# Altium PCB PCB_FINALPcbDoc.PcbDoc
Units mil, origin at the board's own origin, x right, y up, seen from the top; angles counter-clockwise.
Board outline 2408.25 x 1826.41 mil, 2 copper layers (Top Layer, Bottom Layer); 49 components, 43 nets, 223 pads, 93 vias.
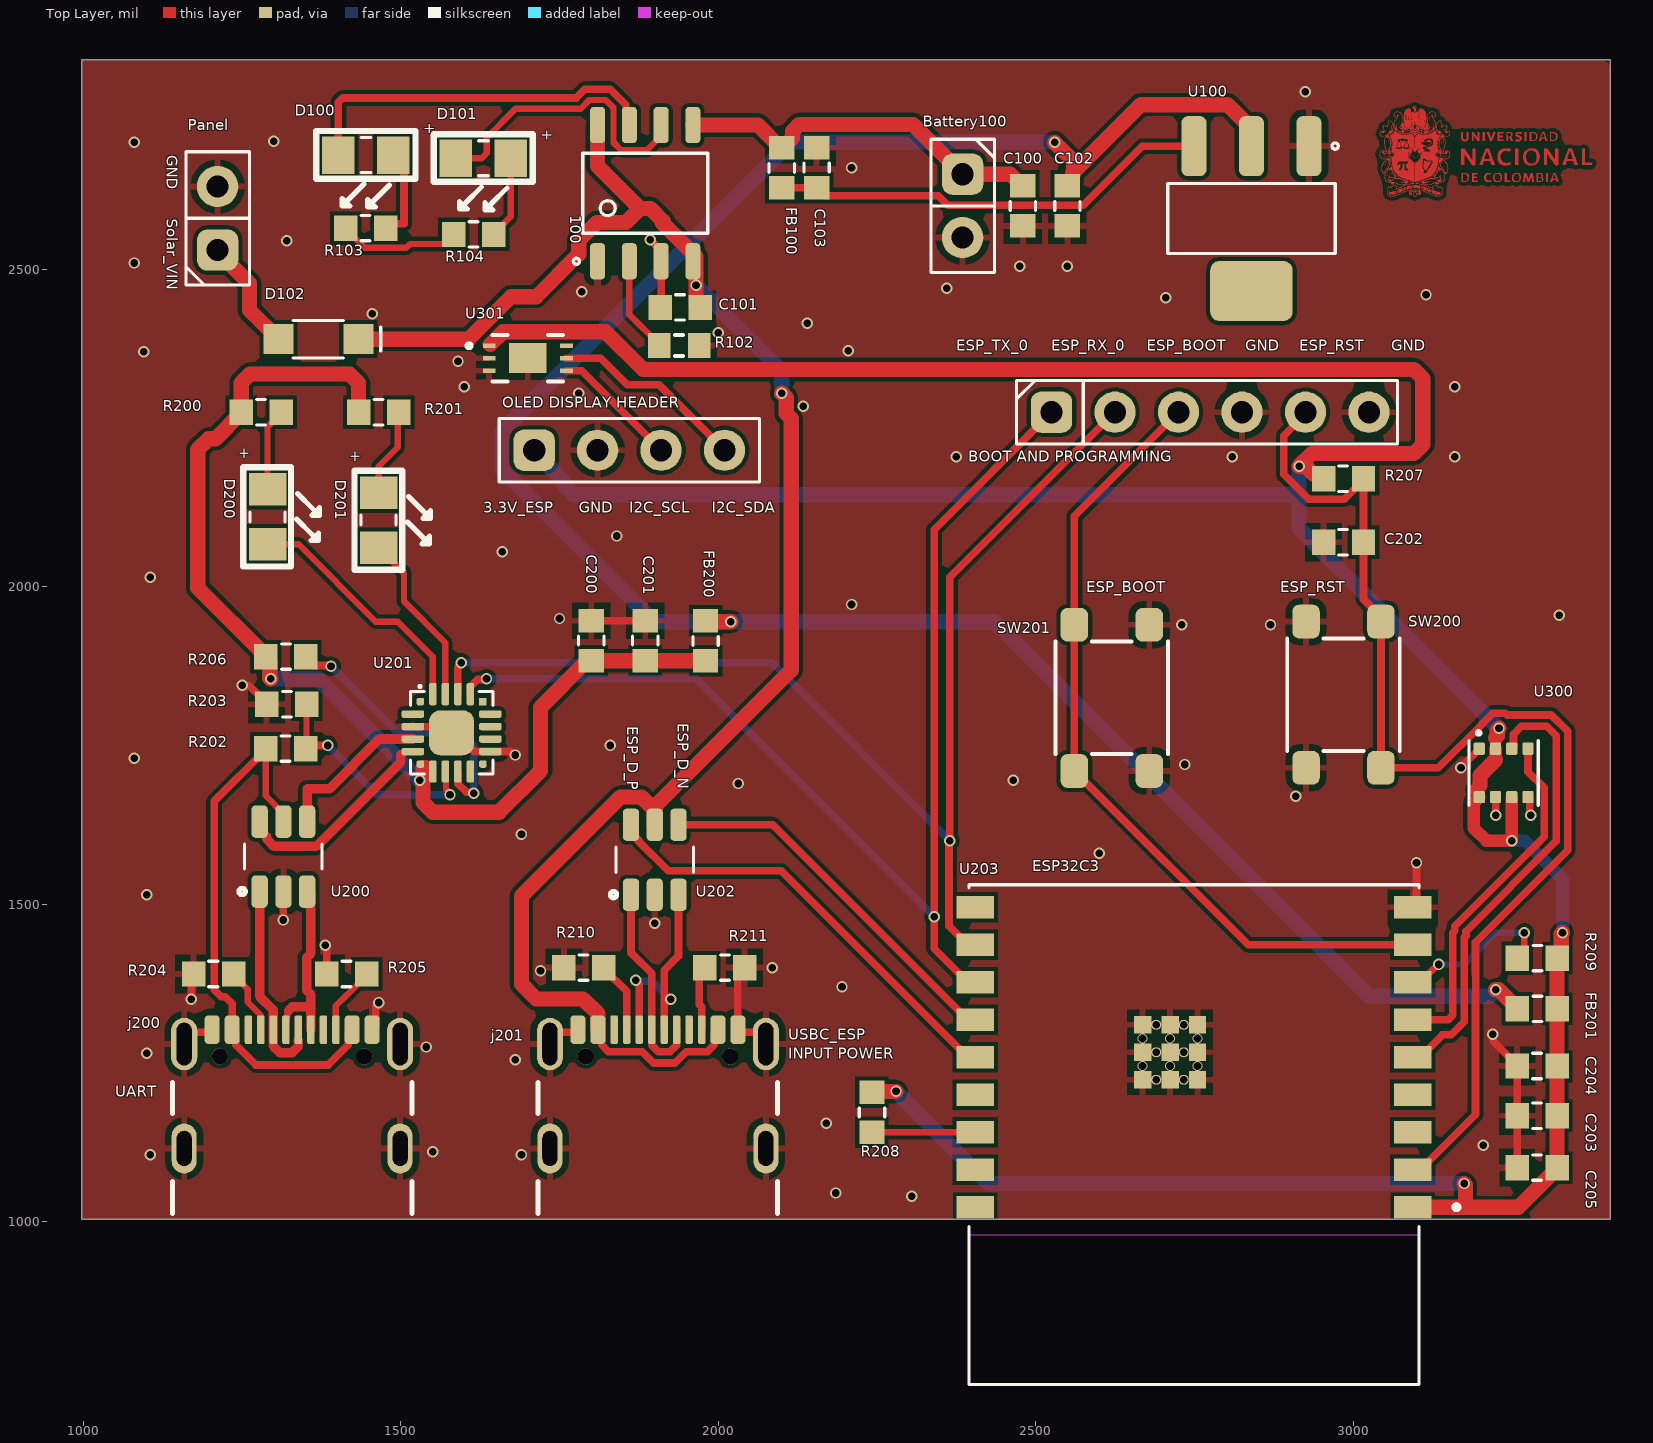
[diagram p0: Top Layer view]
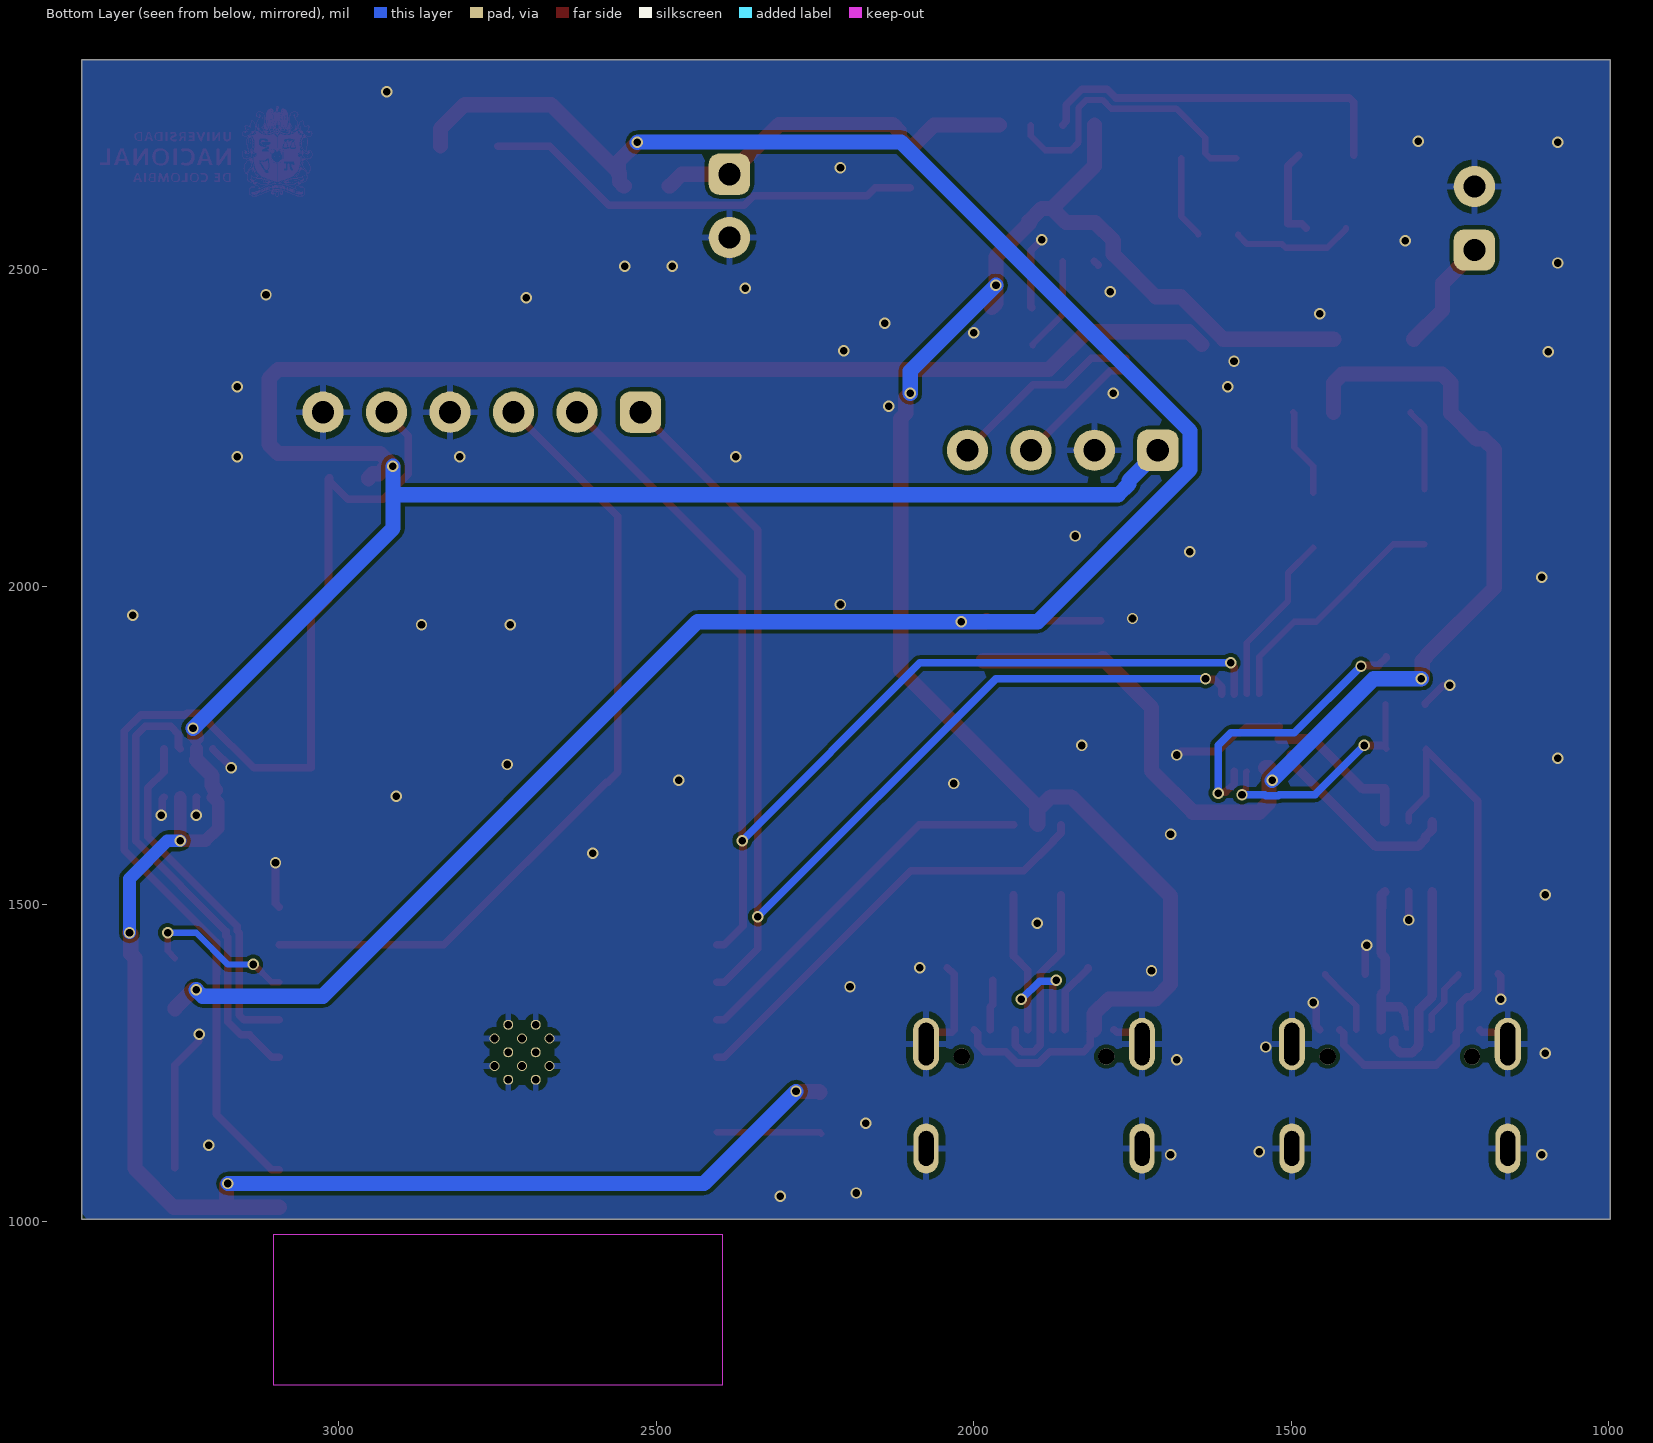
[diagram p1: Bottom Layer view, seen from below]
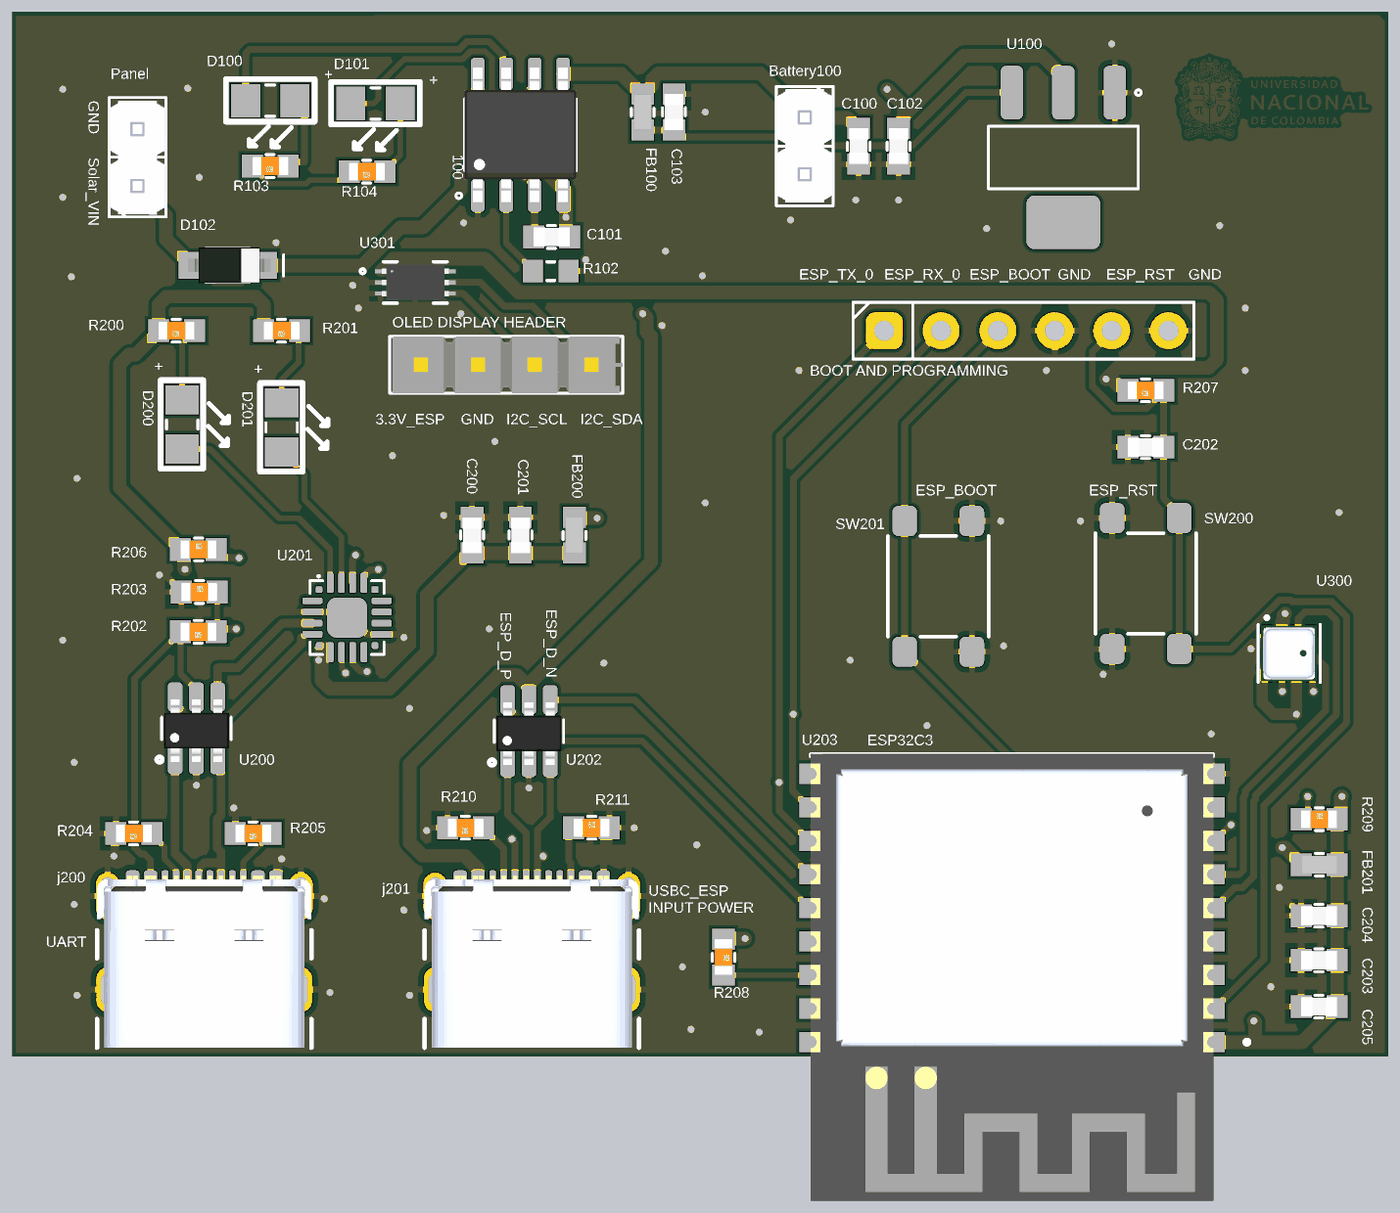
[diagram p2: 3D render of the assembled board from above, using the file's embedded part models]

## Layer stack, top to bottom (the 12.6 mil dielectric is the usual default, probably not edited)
Top Solder: solder mask 0.4, Solder Resist, Dk 3.5
Top Layer: signal copper 1.4
Dielectric 1: dielectric 12.6, FR-4, Dk 4.8
Bottom Layer: signal copper 1.4
Bottom Solder: solder mask 0.4, Solder Resist, Dk 3.5

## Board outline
997.15,1003.59 997.15,2830 3405.4,2830 3405.4,2762.11 3405.4,1592.11 3405.4,1007.11 3405,1003.59

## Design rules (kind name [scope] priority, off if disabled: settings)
AcuteAngle [All] p1: minimum=6.00000000000000E+0001 checktracksonly=FALSE
Clearance [All] p1: gap=6 ignorepadtopadclearanceinfootprint=TRUE
DiffPairsRouting [All] p1: maxlimit=10 minlimit=10 mostfreqgap=10 toplayer_minwidth=15 toplayer_maxwidth=15 toplayer_prefwidth=15 bottomlayer_minwidth=15 bottomlayer_maxwidth=15 bottomlayer_prefwidth=15 maxuncoupledlength=500
HoleSize [All] p1: absolutevalues=TRUE maxlimit=100 minlimit=12 maxpercent=80.000 minpercent=20.000
HoleToHoleClearance [All] p1: gap=5 allowstackedmicrovias=TRUE
MinimumSolderMaskSliver [All] p1: minsoldermaskwidth=2
PolygonConnect PolygonConnect_Via [IsVia] p1: connectstyle=Direct reliefconductorwidth=10 reliefentries=4 polygonreliefangle="90 Angle" airgapwidth=10
PolygonConnect [All] p2: connectstyle=Relief reliefconductorwidth=10 reliefentries=4 polygonreliefangle="90 Angle" airgapwidth=10
RoutingVias [All] p1: holewidth=12 width=18 viastyle="Through Hole" minholewidth=12 minwidth=18 maxholewidth=50 maxwidth=100
SilkToSilkClearance [All] p1: silktosilkclearance=1
SilkToSolderMaskClearance [IsPad] p1: minsilkscreentomaskgap=1 clearancetoexposedcopper=TRUE
SolderMaskExpansion [All] p1: expansion=2 istentingtop=FALSE
SupplyNets "Schematic Supply Nets_1" [InNet('Solar_VIN')] p1: voltage=0.000
SupplyNets "Schematic Supply Nets_9" [InNet('VBUS_ESP')] p2: voltage=0.000
SupplyNets "Schematic Supply Nets_8" [InNet('VUSB')] p3: voltage=0.000
SupplyNets "Schematic Supply Nets_7" [InNet('3.3V_ESP')] p4: voltage=0.000
SupplyNets "Schematic Supply Nets_6" [InNet('3.3V_CP')] p5: voltage=0.000
SupplyNets "Schematic Supply Nets_5" [InNet('BAT+')] p6: voltage=0.000
SupplyNets "Schematic Supply Nets_4" [InNet('5V_USB')] p7: voltage=0.000
SupplyNets "Schematic Supply Nets_3" [InNet('3.3V')] p8: voltage=0.000
SupplyNets "Schematic Supply Nets" [InNet('GND')] p9: voltage=0.000
Width [All] p1: maxlimit=80 minlimit=10 preferedwidth=10
24 further rules are at their usual default settings.

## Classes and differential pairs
component class "Sensors And Oled": "OLED DISPLAY HEADER" U300 U301
component class Power: 100 Battery100 C100 C101 C102 C103 D100 D101 D102 FB100 Panel R102 R103 R104 U100
component class ESP32C3: "BOOT AND PROGRAMMING" C200 C201 C202 C203 C204 C205 D200 D201 FB200 FB201 j200 j201 R200 R201 R202 R203 R204 R205 R206 R207 R208 R209 R210 R211 SW200 SW201 U200 U201 U202 U203
differential pair USB_O_CP_D: +USB_O_CP_D_P -USB_O_CP_D_N
differential pair USB_CP_D: +USB_CP_D_P -USB_CP_D_N

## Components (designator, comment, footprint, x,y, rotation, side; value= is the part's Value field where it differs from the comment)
100 "4.2V 1A" SOIC_8_3.9mm 1885,2620 r90 top
Battery100 "2x1" H_2x1_TH_100mil 2385,2600 r270 top
"BOOT AND PROGRAMMING" "6x1" H_6x1_TH_100mil 2775,2275 r0 top (schematic designator H200)
C100 "1uF 50V" 0603_cap 2480,2600 r270 top value=1uF
C101 "1uF 50V" 0603_cap 1940,2440 r180 top value=1uF
C102 "22uF 10V" 0603_cap 2550,2600 r270 top value=22uF
C103 "10uF 10V" 0603_cap 2155,2660 r90 top value=10uF
C200 "10uF 10V" 0603_cap 1800,1915 r90 top value=10uF
C201 "0.1uF 50V" 0603_cap 1885,1915 r90 top value=0.1uF
C202 "10uF 10V" 0603_cap 2985,2070 r180 top value=10uF
C203 "10uF 10V" 0603_cap 3290,1166.72 r180 top value=10uF
C204 "0.1uF 50V" 0603_cap 3290,1245 r180 top value=0.1uF
C205 "0.1uF 50V" 0603_cap 3290,1085 r180 top value=0.1uF
D100 "2V" 0805_LED 1445,2680 r180 top
D101 "2.9V" 0805_LED 1630,2675 r180 top
D102 "40V 1A" SOD_123 1370,2390 r180 top
D200 "2.9V" 0805_LED 1290,2110 r270 top
D201 "2V" 0805_LED 1465,2105 r270 top
FB100 "60OHM 2A" 0603_fb 2100,2660 r270 top value="60 OHM"
FB200 "60OHM 2A" 0603_fb 1980,1915 r270 top value="60 OHM"
FB201 "60OHM 2A" 0603_fb 3290,1335 r0 top value="60 OHM"
j200 "USB C" CON_USB_C_16P_RA 1328.78,1208.72 r0 top
j201 "USB C" CON_USB_C_16P_RA 1905,1208.72 r0 top
"OLED DISPLAY HEADER" "4x1" H_4x1_TH_2.54mm 1860,2215 r0 top (schematic designator H300)
Panel "2x1" H_2x1_TH_100mil 1211.4,2580.4 r90 top
R102 "2K 0603" 0603_resistor 1938.5,2380 r0 top value=2k
R103 "1k 1/10W" 0603_res 1445,2565 r180 top value=1k
R104 "1k 1/10W" 0603_res 1615,2555 r180 top value=1k
R200 "84R5 1/10W" 0603_res 1280,2275 r180 top value=84R5
R201 "150R 1/10W" 0603_res 1465,2275 r180 top value=150R
R202 "3k3 1/10W" 0603_res 1318.5,1745 r180 top value=3k3
R203 "4k7 1/10W" 0603_res 1320,1815 r0 top value=4k7
R204 "5.1K 1/10W" 0603_res 1205,1390 r180 top value=5.1K
R205 "5.1K 1/10W" 0603_res 1415,1390 r180 top value=5.1K
R206 "1k 1/10W" 0603_res 1318.5,1890 r0 top value=1k
R207 "1k 1/10W" 0603_res 2985,2170 r180 top value=1k
R208 "10k 1/10W" 0603_res 2242.21,1172.21 r270 top value=10k
R209 "10k 1/10W" 0603_res 3290,1415 r0 top value=10k
R210 "5.1K 1/10W" 0603_res 1788.5,1400 r180 top value=5.1K
R211 "5.1K 1/10W" 0603_res 2010,1400 r0 top value=5.1K
SW200 "Sw" Sw_PUSH_4.5x4.5x5mm 2985,1830 r90 top
SW201 "Sw" Sw_PUSH_4.5x4.5x5mm 2620,1825 r90 top
U100 "AMS1117-3.3" SOT_223 2840,2580 r270 top
U200 "USBLC6-2SC6" SOT_23_6 1315,1575 r90 top
U201 "CP2102N-A02-GQFN20R" WFQFN_20_EP_3X3MM 1580,1770 r0 top
U202 "USBLC6-2SC6" SOT_23_6 1900,1570 r90 top
U203 "ESP32-C3-WROOM-02-N4" ESP32-C3-WROOM-02-N4 2749.49,1258.82 r180 top
U300 "SENSOR_HUM_TEMP" BME280_SENSOR_TEMP_HUM 3237.2,1706.81 r90 top
U301 "BH17-Sensor" BH1750FVI-TR_ROM 1700,2360 r0 top

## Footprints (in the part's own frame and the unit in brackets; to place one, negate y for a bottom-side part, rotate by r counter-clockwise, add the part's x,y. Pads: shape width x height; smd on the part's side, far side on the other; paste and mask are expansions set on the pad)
0603_cap [mil]
  rect 37x40 smd: 1(-31.5,0) 2(31.5,0)
  silkscreen extent -7,-20 8,20, body extent -31,-17 31,17, height 34
0603_fb [mil]
  rect 37x40 smd: 1(-31.5,0) 2(31.5,0)
  silkscreen extent -7,-20 8,20, body extent -32,-16 31,16, height 32
0603_res [mil] "1608 Metric / 20190225 / C-A.Serna.A"
  rect 37x40 smd: 1(-31.5,0) 2(31.5,0)
  silkscreen extent -7,-20 8,20, body extent -31,-16 32,16, height 12
0603_resistor [mm]
  rect 0.9x1 smd: 1(-0.8,0) 2(0.8,0)
  silkscreen extent -0.16,-0.42 0.16,0.42, body extent -0.84,-1.27 1.11,0.42, height 0.8
0805_LED [mm]
  rect 1.3x1.5 smd: 1(-1.1,0) 2(1.1,0)
  silkscreen extent -1.98,-0.97 1.98,2.07, body extent -1,-0.62 1,0.63, height 1.1
BH1750FVI-TR_ROM [mm] "SENSOR OPT 560NM AMBIENT 6WSOF"
  rect 0.503x0.179 smd paste+0 mask+0: 1(-1.548,0.5) 2(-1.548,0) 3(-1.548,-0.5) 4(1.548,-0.5) 5(1.548,0) 6(1.548,0.5)
  rect 1.5x1.2 smd paste+0 mask+0: 7(0,0)
  silkscreen extent -2.45,-0.93 1.42,0.93, body extent -1.5,-0.8 1.5,0.8, height 0.76
BME280_SENSOR_TEMP_HUM [mm] "Sensor Temperature Humedad"
  rrect25% 0.49x0.45 smd paste+0 mask+0.102: 1(0.97,0.975) 2(0.97,0.325) 3(0.97,-0.325) 4(0.97,-0.975) 5(-0.97,-0.975) 6(-0.97,-0.325) 7(-0.97,0.325) 8(-0.97,0.975)
  silkscreen extent -1.3,-1.39 1.65,1.39, body extent -1.25,-1.25 1.25,1.25, height 1
CON_USB_C_16P_RA [mm]
  oval 1x2 hole 0.6 slot 1.4 at 90 deg: 0(-4.32,-2.377) 0(4.32,-2.377)
  oval 1.05x2.1 hole 0.6 slot 1.7 at 90 deg: 0(-4.32,1.803) 0(4.32,1.803)
  rrect50% 0.6x1.15 smd: A1/B12(-3.2,2.378) A4/B9(-2.4,2.378) B1/A12(3.2,2.378) B4/A9(2.4,2.378)
  rrect50% 0.3x1.15 smd: A5(-1.25,2.378) A6(-0.25,2.378) A7(0.25,2.378) A8(1.25,2.378) B5(1.75,2.378) B6(0.75,2.378) B7(-0.75,2.378) B8(-1.75,2.378)
  round 0.65 hole 0.65 unplated: ""(-2.89,1.303) ""(2.89,1.303)
  silkscreen extent -4.79,-4.98 4.79,0.27, body extent -4.79,-4.98 4.79,2.73, height 3.31
ESP32-C3-WROOM-02-N4 [mm]
  rect 1.5x0.9 smd: 1(-8.75,6) 2(-8.75,4.5) 3(-8.75,3) 4(-8.75,1.5) 5(-8.75,0) 6(-8.75,-1.5) 7(-8.75,-3) 8(-8.75,-4.5) 9(-8.75,-6) 10(8.75,-6) 11(8.75,-4.5) 12(8.75,-3) 13(8.75,-1.5) 14(8.75,0) 15(8.75,1.5) 16(8.75,3) 17(8.75,4.5) 18(8.75,6)
  rect 0.7x0.7 smd: 19(-0.14,0.9) 19(-0.14,-0.2) 19(-0.14,-1.3) 19(0.96,0.9) 19(0.96,-0.2) 19(0.96,-1.3) 19(2.06,-1.3) 19(2.06,-0.2) 19(2.06,0.9)
  round 0.4 hole 0.305 mask+0: 19(-0.14,0.35) 19(-0.14,-0.75) 19(0.41,0.9) 19(0.41,-0.2) 19(0.41,-1.3) 19(0.96,0.35) 19(0.96,-0.75) 19(1.51,0.9) 19(1.51,-0.2) 19(1.51,-1.3) 19(2.06,-0.75) 19(2.06,0.35)
  Keep-Out Layer region: 9,7.1 -9,7.1 -9,13.1 9,13.1
  Keep-Out Layer region: 9,7.1 -9,7.1 -9,13.1 9,13.1
  silkscreen extent -10.6,-6.9 9,13.1, body extent -9,-6.9 9,13.1, height 3.35
H_2x1_TH_100mil [mil]
  rrect50% 65x65 hole 35: 1(-50,0)
  round 65 hole 35: 2(50,0)
  silkscreen extent -105,-50 105,50, body extent -101,-49 99,49, height 339
H_4x1_TH_2.54mm [mil]
  rrect50% 65x65 hole 35: 1(-150,0)
  round 65 hole 35: 2(-50,0) 3(50,0) 4(150,0)
  silkscreen extent -205,-50 205,50, body extent -200,-50 205,50, height 420
H_6x1_TH_100mil [mil]
  rrect50% 65x65 hole 35: 1(-250,0)
  round 65 hole 35: 2(-150,0) 3(-50,0) 4(50,0) 5(150,0) 6(250,0)
  silkscreen extent -305,-50 295,50
SOD_123 [mm]
  rect 1.2x1.2 smd: 1(-1.6,0) 2(1.6,0)
  silkscreen extent -2.5,-0.75 1,0.75, body extent -1.93,-0.8 1.77,0.8, height 1.28
SOIC_8_3.9mm [mm]
  rrect50% 1.45x0.6 smd: 1(-2.725,1.905) 2(-2.725,0.635) 3(-2.725,-0.635) 4(-2.725,-1.905) 5(2.725,-1.905) 6(2.725,-0.635) 7(2.725,0.635) 8(2.725,1.905)
  silkscreen extent -2.85,-2.5 1.6,2.88, body extent -3.01,-2.5 3.01,2.5, height 1.73
SOT_23_6 [mm]
  rrect50% 1.3x0.65 smd: 1(-1.4,0.95) 2(-1.4,0) 3(-1.4,-0.95) 4(1.4,-0.95) 5(1.4,0) 6(1.4,0.95)
  silkscreen extent -1.52,-1.55 0.5,1.78, body extent -1.5,-1.45 1.3,1.45, height 1.45
SOT_223 [mm]
  rrect50% 2.4x1 smd: 1(-2.9,2.3) 2(-2.9,0) 3(-2.9,-2.3)
  rrect30% 2.4x3.3 smd: 4(2.9,0)
  silkscreen extent -3.02,-3.35 1.4,3.48, body extent -1.86,-3.35 1.86,3.35, height 1.8
Sw_PUSH_4.5x4.5x5mm [mm]
  rrect50% 1.35x1.1 smd: 1(-2.925,1.5) 1(2.925,1.5) 2(-2.925,-1.5) 2(2.925,-1.5)
  silkscreen extent -2.25,-2.25 2.25,2.25, body extent -2.25,-2.25 2.25,2.25, height 5
WFQFN_20_EP_3X3MM [mm]
  rrect50% 0.3x0.3 smd mask+0.051: 1(-1.25,1.25) 6(-1.25,-1.25) 11(1.25,-1.25)
  rrect50% 0.9x0.3 smd mask+0.051: 2(-1.55,0.75) 3(-1.55,0.25) 4(-1.55,-0.25) 5(-1.55,-0.75) 12(1.55,-0.75) 13(1.55,-0.25) 14(1.55,0.25) 15(1.55,0.75)
  rrect50% 0.3x0.9 smd mask+0.051: 7(-0.75,-1.55) 8(-0.25,-1.55) 9(0.25,-1.55) 10(0.75,-1.55) 17(0.75,1.55) 18(0.25,1.55) 19(-0.25,1.55) 20(-0.75,1.55)
  rect 0.3x0.3 smd mask+0.051: 16(1.25,1.25)
  rrect50% 1.8x1.8 smd mask+0.051: 21(0,0)
  silkscreen extent -1.65,-1.65 1.65,1.9, body extent -1.5,-1.5 1.5,1.5, height 0.8

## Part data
100: library part IC_BAT_CHG_4.2V_1A, "-300mV~8V Lithium-ion/Polymer 1 1A ESOP-8 Battery Management ROHS", Manufacturer=YONGYUTAI, Manufacturer Part Number=TP4056, Supplier Part Number 1=C20199357
Battery100 Panel: library part H_Male_2x1_TH_100mil, "H_Male_2x1_TH_100mil"
"BOOT AND PROGRAMMING": library part H_Male_6x1_TH_100mil, "H_Male_6x1_TH_100mil"
C100 C101: library part Cap_1uF_0603_50V, "50V 1uF X5R ±10% 0603 Multilayer Ceramic Capacitors MLCC - SMD/SMT ROHS", Manufacturer="Samsung Electro-Mechanics", Manufacturer Part Number=CL10A105KB8NNNC, Supplier Part Number 1=C15849
C102: library part Cap_22uF_0603_10V, "10V 22uF X5R ±20% 0603 Multilayer Ceramic Capacitors MLCC - SMD/SMT ROHS", Manufacturer=HRE, Manufacturer Part Number=CGA0603X5R226M100JT, Supplier Part Number 1=C6119863
C103 C200 C202 C203: library part Cap_10uF_0603_10V, "10V 10uF X5R ±10% 0603 Multilayer Ceramic Capacitors MLCC - SMD/SMT ROHS", Manufacturer=CCTC, Manufacturer Part Number=TCC0603X5R106K100CT, Supplier Part Number 1=C380314
C201 C204 C205: library part Cap_0.1uF_0603_50V, "50V 100nF Y5V -20%~+80% 0603 Multilayer Ceramic Capacitors MLCC - SMD/SMT ROHS", Manufacturer="Walsin Tech Corp", Manufacturer Part Number=0603F104Z500CT, Supplier Part Number 1=C83060
D100 D201: library part LED_0805_RED, "LED RED CLEAR 0805 SMD", Manufacturer=XINGLIGHT, Manufacturer Part Number=XL-2012SURC, Supplier Part Number 1=C965812
D101 D200: library part LED_0805_Green, "LED GREEN CLEAR 0805 SMD", Manufacturer=XINGLIGHT, Manufacturer Part Number=XL-2012UGC, Supplier Part Number 1=C965815
D102: library part D_Schottky_40V_1A_SOD_123F, "DIODE SCHOTTKY 40V 1A SOD123F", Manufacturer="Shanghai Prisemi Elec", Manufacturer Part Number=PSBD1DF40V1H, Supplier Part Number 1=C110730
FB100 FB200 FB201: library part FB_60_0603_2A, "2A 1 100mΩ 60Ω@100MHz ±25% 0603 Ferrite Beads ROHS", Manufacturer=TAI-TECH, Manufacturer Part Number=HCB1608KF-600T20, Supplier Part Number 1=C369516
j200 j201: library part CON_USB_TYPEC_16P, "3A USB 3.1 1 Surface Mount 16P Female -40℃~+85℃ Type-C SMD USB Connectors ROHS", Manufacturer="SHOU HAN", Manufacturer Part Number=TYPE-C-3.1-16PIN, Supplier Part Number 1=C7507405
"OLED DISPLAY HEADER": library part H_Male_4x1_TH_100mil, "H_Male_4x1_TH_100mil"
R102: library part RES_2K_0603_1/10W_1%_1, "RES 2K OHM 1% 1/10W 0603", Manufacturer="NIC Components Corp", Manufacturer PN=NRC06F2001TRF, Supplier Part Number 1=4988-NRC06F2001TRFCT-ND
R103 R104 R206 R207: library part Res_1k_0603_1/10W, "RES SMD 1k OHM 5% 1/10W 0603", Manufacturer=FOJAN, Manufacturer Part Number="FRC0603J102 TS", Supplier Part Number 1=C2907113
R200: library part Res_84R5_0603_1/10W, "100mW Thick Film Resistor 50V ±100ppm/℃ ±1% 84.5Ω 0603 Chip Resistor - Surface Mount ROHS", Manufacturer="LIZ Elec", Manufacturer Part Number=CR0603FA84R5G, Supplier Part Number 1=C101216
R201: library part Res_150R_0603_1/10W, "100mW Thick Film Resistor 75V ±100ppm/℃ ±1% 150Ω 0603 Chip Resistor - Surface Mount ROHS", Manufacturer=RALEC, Manufacturer Part Number=RTT031500FTP, Supplier Part Number 1=C103302
R202: library part Res_3k3_0603_1/10W, "RES SMD 3k3 OHM 5% 1/10W 0603", Manufacturer=FOJAN, Manufacturer Part Number="FRC0603J332 TS", Supplier Part Number 1=C2907140
R203: library part Res_4k7_0603_1/10W, "100mW Thick Film Resistor 75V ±1% 4.7kΩ 0603 Chip Resistor - Surface Mount ROHS", Manufacturer=VO, Manufacturer Part Number=SCR0603F4K7, Supplier Part Number 1=C3016318
R204 R205 R210 R211: library part Res_5.1K_0603_1/10W, "5.1 kOhms ±1% 0.1W, 1/10W Chip Resistor 0603 (1608 Metric) Automotive AEC-Q200 Thick Film", Manufacturer="KOA Speer Electronics, Inc.", Manufacturer Part Number=RK73H1JTTD5101F, Supplier Part Number 1=2019-RK73H1JTTD5101FCT-ND
R208 R209: library part Res_10k_0603_1/10W, "RES SMD 10k OHM 5% 1/10W 0603", Manufacturer=FOJAN, Manufacturer Part Number=FRC0603J103TS, Supplier Part Number 1=C2930027
SW200 SW201: library part Sw_PUSH_4.5x4.5x5.0xmm, "SWITCH TACTILE SPST-NO 0.05A 12V", Manufacturer=BZCN, Manufacturer Part Number=TSC015A05026A, Supplier Part Number 1=C2888509
U100: library part LDO_3V3_1A_FIXED, "1A 60dB@(120Hz) Fixed 3.3V Positive 18V SOT-223 Linear Voltage Regulators (LDO) ROHS", Manufacturer="UMW(Youtai Semiconductor Co., Ltd.)", Supplier Part Number 1=C347222
U200 U202: library part TVS_5.25V_2CH_SOT_23_6, "TVS DIODE 5.25V 17V SOT23-6", Manufacturer=STMicroelectronics, Supplier Part Number 1=C7519
U201: library part IC_SGL_USB2UART-BRIDGE_20QFN, "IC USB TO UART BRIDGE QFN20", Manufacturer="Silicon Labs", Supplier Part Number 1=C969913
U203: library part MCU_ESP32-C3-WROOM-02-N4, "RF TXRX MOD BT WIFI PCB TH SMD", Manufacturer="Espressif Systems", Supplier Part Number 1=C2934560
U300: library part BME280_SENSOR_HUM_TEMP, "SENSOR PRESSURE HUMIDITY TEMP", Manufacturer="Bosch Sensortec", Manufacturer PN=BME280, Supplier Part Number 1=828-1063-1-ND
U301: library part BH1750FVI-TR, "SENSOR OPT 560NM AMBIENT 6WSOF", Manufacturer="Rohm Semiconductor", Supplier Part Number 1=BH1750FVICT-ND

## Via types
v1: diameter 18, hole 12, Top Layer to Bottom Layer, tented both sides, 93 vias

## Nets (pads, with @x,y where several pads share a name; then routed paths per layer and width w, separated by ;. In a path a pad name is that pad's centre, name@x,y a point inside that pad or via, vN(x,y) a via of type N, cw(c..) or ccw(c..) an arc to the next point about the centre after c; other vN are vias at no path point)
3.3V: C102.1 FB200.1 FB201.1 U100.2 | length 3600.8
  Top Layer w24: FB200.1 1981.5,1945 v1(2020,1945) ; v1(2530,2700) 2560,2670 2560,2652.06 2558,2650.06 C102.1@2558,2638 ; U100.2 2840,2721.73 2802.31,2759.42 2665.92,2759.42 2558,2651.5 C102.1@2558,2638 ; v1(3225,1365) 3230,1365 3258.5,1336.5 FB201.1 ; C102.1@2551.5,2631.5 C102.1 C102.1@2551.5,2631.5 ; C102.1@2551.5,2631.5 C102.1@2558,2638 ; C102.1@2551.5,2631.5 C102.1@2558,2638
  Bottom Layer w24: v1(2530,2700) 2529.5,2700.5 2114.56,2700.5 1659.5,2245.44 1659.5,2184.56 1899.06,1945 v1(2020,1945) 2435,1945 3025,1355 3215,1355 v1(3225,1365)
3.3V_CP: C200.1 C201.1 FB200.2 R200.2 R201.2 R206.1 U201.6 U201.7 | length 1763.9
  Top Layer w24: v1(1295,1855) 1293.5,1856.5 1293.5,1883.5 R206.1 1287,1891.5 1180,1998.5 1180,2215.94 1197.12,2233.06 1208.06,2233.06 1248.5,2273.5 R200.2 1248.5,2320.94 1262.56,2335 1419.44,2335 1433.5,2320.94 R201.2 ; 1540,1715 1535,1715 1535,1660 1550.06,1644.94 1654.94,1644.94 1720,1710 1720,1810 C200.1@1796.75,1886.75 ; C200.1 C201.1 FB200.2@1985,1883.5
  Bottom Layer w24: v1(1295,1855) 1370,1855 v1(1530,1695)
3.3V_ESP: "OLED DISPLAY HEADER.1" C203.1 C204.1 C205.1 FB201.2 R207.2 R208.1 R209.2 U203.1 U300.2 U300.6 U300.8 U301.1 | length 5785.3
  Top Layer w20: U300.8 3190,1659.8 3190,1620 3210,1600 v1(3250,1600) U300.6 ; 3224.41,1727.2 U300.2
  Top Layer w24: U301.1@1640.87,2381.52 1660.98,2401.62 1822.53,2401.62 1881.84,2342.31 3095.94,2342.31 3110,2328.26 3110,2224.06 3095.94,2210 2935,2210 v1(2915,2190) 2925,2190 2937,2178 2947,2178 2953.5,2171.5 R207.2 ; R208.1 2243.5,1205 v1(2280,1205) ; U203.1 3177.29,1022.6 ; v1(3175,1060) 3177.29,1057.71 3177.29,1022.6 ; 3195,1680 3197.55,1682.55 3197.55,1684.43 3199.99,1686.87 3199.99,1702.79 3224.41,1727.2 ; 3224.41,1762.07 3227.2,1764.87 3227.2,1774.2 v1(3230,1777) ; v1(3330,1455) 3328,1453 3328,1421.5 R209.2 FB201.2 C204.1 C203.1 C205.1 3321.5,1083.5 3260.6,1022.6 3177.29,1022.6
  Bottom Layer w20: v1(3250,1600) 3270,1600 3330,1540 v1(3330,1455)
  Bottom Layer w24: 1710,2215 1710,2212.7 1755.46,2167.24 1755.46,2161.97 1772.43,2145 2911,2145 2915,2141 ; v1(2280,1205) 2425,1060 v1(3175,1060) ; v1(2915,2190) 2915,2141 ; v1(3230,1777) 2915,2092 2915,2141
5V_USB: R103.2 R104.2 | length 193.3
  Top Layer w10: R103.2 1413.5,2563.5 1443,2534 1508.72,2534 1514.72,2540 1570,2540 1583.5,2553.5 R104.2
BAT+: 100.5 Battery100.1 C100.1 FB100.1 | length 596
  Top Layer w24: 100.5 2062.72,2727.28 2098.5,2691.5 FB100.1 2101.5,2691.5 2117,2707 2117,2717.46 2127.54,2728 2307,2728 Battery100.1 2460,2650 2478.5,2631.5 C100.1
CHRG: 100.7 D100.2 | length 588.9
  Top Layer w12: D100.2 1401.69,2762.97 1408.72,2770 1776.22,2770 1790.05,2783.83 1829.95,2783.83 1854.19,2759.59 1854.19,2733.09 100.7
ESP_BOOT: "BOOT AND PROGRAMMING.3" SW201.1 U203.8 | length 1278.6
  Top Layer w12: SW201.1@2560.94,1707.53 2576.23,1692.25 2578.54,1692.25 2834.8,1435.98 U203.8 ; SW201.1@2560.94,1709.84 2560.94,1940.16 2560.94,2110.94 2725,2275
ESP_D_N: U202.4 U203.13 | length 594.9
  Top Layer w12: U202.4 2085.95,1625.12 2393.19,1317.87 U203.13
ESP_D_P: U202.6 U203.14 | length 702.5
  Top Layer w12: U202.6 1862.6,1612.11 1875.2,1599.51 1875.2,1598.3 1921.03,1552.47 2099.54,1552.47 2393.19,1258.82 U203.14
ESP_RST: "BOOT AND PROGRAMMING.5" C202.1 R207.1 SW200.2 U203.2 | length 1876
  Top Layer w12: 2925,2275 2925,2271.58 2891,2237.58 2891,2177.03 2930.03,2138 2986,2138 3015,2167 R207.1@3015,2171.5 ; R207.1 C202.1 3016.5,1980.25 3044.06,1952.69 3044.06,1945.16 3044.06,1714.84 3134.48,1714.84 3203.2,1783.56 3203.2,1784.15 3220.06,1801 3239.94,1801 3242.94,1798 3312.46,1798 3338,1772.46 3338,1584.97 3193,1439.97 3193,1390.03 3193.12,1389.91 3193.12,1360.09 3193,1359.97 3193,1168.87 3105.79,1081.65 U203.2
ESP_RX_0: "BOOT AND PROGRAMMING.2" U201.18 U203.11 | length 1908.6
  Top Layer w12: U201.18 1589.84,1873.22 1595,1878.38 v1(1595,1880) ; U203.11 2393.19,1435.98 2363.47,1465.7 2363.47,1595.85 2363.85,1596.23 2363.85,1598.85 v1(2365,1600) 2365,2015 2625,2275
  Bottom Layer w12: v1(1595,1880) 2085,1880 v1(2365,1600)
ESP_TX_0: "BOOT AND PROGRAMMING.1" U201.17 U203.12 | length 1909.1
  Top Layer w12: U201.17 1609.53,1842.65 1620.73,1853.85 1633.85,1853.85 v1(1635,1855) ; U203.12 2393.19,1376.93 2340,1430.12 v1(2340,1480) 2340,2090 2525,2275
  Bottom Layer w12: v1@1636.99,1855 1965,1855 v1(2340,1480)
GND: 100.1 100.3 "BOOT AND PROGRAMMING.4" "BOOT AND PROGRAMMING.6" "OLED DISPLAY HEADER.2" Battery100.2 C100.2 C101.2 C102.2 C103.2 C200.2 C201.2 C202.2 C203.2 C204.2 C205.2 j200.0 j200.A1/B12 j200.B1/A12 j201.0 j201.A1/B12 j201.B1/A12 Panel.2 R102.2 R203.1 R204.2 R205.2 R210.2 R211.2 SW200.1 SW201.2 U100.1 U200.2 U201.3 U201.12 U201.21 U202.2 U203.9 U203.19 U300.1 U300.5 U300.7 U301.2 U301.3 U301.7 | length 1304.3
  Top Layer w12: j200.0@1158.7,1279.68 1158.7,1284.79 1172.25,1298.34 1198.81,1298.34 j200.A1/B12 ; v1(1170,1350) 1170,1386.5 R204.2 ; v1(1250,1845) 1251.15,1843.85 1261.15,1843.85 1288.5,1816.5 R203.1 ; v1(1315,1475) U200.2 ; v1(1380.74,1435) 1380.74,1433.38 1383.5,1430.62 R205.2 ; j200.B1/A12 1460.57,1308.13 1460.57,1338.95 1465,1343.38 v1(1465,1345) ; U201.3 1519.07,1779.75 1570.25,1779.75 U201.21 1586.34,1770 1615.77,1740.57 1640.93,1740.57 U201.12 1672.9,1740.47 1678.38,1735 v1(1680,1735) ; j201.0@1724.61,1290 1734.92,1279.68 1734.92,1284.79 1748.47,1298.34 1775.03,1298.34 j201.A1/B12 ; C200.2 C201.2 ; 100.1@1804.19,2506.91 100.1 ; v1(1892.63,2546.82) 1910,2529.45 100.3 1910,2441.5 C101.2 ; R211.2 2030.98,1389.48 j201.B1/A12 2034.97,1298.34 2061.53,1298.34 2075.08,1284.79 j201.0@2075.08,1279.68 ; U203.9 3100,1501.06 v1(3100,1565) ; v1(3170,1715) 3170,1715.39 3198.82,1744.21 U300.1 ; v1(3220,1295) 3221.15,1293.85 3221.15,1283.85 3258.5,1246.5 C204.2 C203.2 C205.2 ; U300.7 3224.7,1668.33 3224.7,1640.3 v1(3225,1640) ; U300.5 3278.45,1665.76 3278.45,1643.17 3280,1641.62 v1(3280,1640)
  other v1: 2305,1040 2185,1045 1105,1105 1690,1105 1550,1110 3205,1120 2170,1155 1680,1255 1100,1265 1540,1275 2195,1370 1720,1395 2085,1400 1900,1470 1100,1515 2600,1580 1690,1610 2910,1670 2031.67,1690.12 2465,1695 2735,1720 1080,1730 1830,1750 2730,1940 2870,1940 1750,1950 3325,1955 2210,1972 1105,2015 1660,2055 1840,2080 2375,2205 2810,2205 3160,2205 2134.09,2284.09 1780,2305 1600,2315 3160,2315 1590,2355 1095,2370 2205,2371.71 2000,2400 2140,2415 1455,2430 2705,2455 3115,2460 1785,2465 2360,2470 2475,2505 2550,2505 1080,2510 1320,2545 2210,2660 1080,2700 1299.64,2701.75 2925,2780
I2C_SCL: "OLED DISPLAY HEADER.3" U301.4 | length 200.9
  Top Layer w12: U301.4 1784.69,2340.32 1910,2215
I2C_SDA: "OLED DISPLAY HEADER.4" U301.5 | length 309.1
  Top Layer w12: U301.5 1814.93,2360 1856.62,2318.31 1906.69,2318.31 2010,2215
Net100_2: 100.2 R102.1 | length 152.2
  Top Layer w10: 100.2 1860,2428.98 1907.01,2381.97 R102.1
NetC103_1: C103.1 FB100.2 U100.3 | length 699.4
  Top Layer w12: FB100.2 C103.1 2167.5,2616 2346.55,2616 2361.55,2601 2574.97,2601 2668.14,2694.17 U100.3
NetD100_1: D100.1 R103.1 | length 146.3
  Top Layer w12: R103.1 1483.53,2572.03 1505,2572.03 1505,2663.31 D100.1
NetD101_1: D101.1 R104.1 | length 131.1
  Top Layer w10: R104.1 1646.5,2556.5 1673.31,2583.31 D101.1
NetD200_1: D200.1 R200.1 | length 130.6
  Top Layer w10: D200.1 1290,2252 1311.5,2273.5 R200.1
NetD200_2: D200.2 U201.20 | length 392.4
  Top Layer w10: D200.2 1293.94,2066.69 1338.94,2066.69 1460.63,1945 1495,1945 1550.47,1889.53 U201.20
NetD201_1: D201.1 R201.1 | length 139.7
  Top Layer w10: D201.1 1465,2190 1495,2220 1495,2273.5 R201.1
NetD201_2: D201.2 U201.19 | length 274.2
  Top Layer w10: D201.2 1505,2021.69 1505,1977.05 1570.16,1911.89 U201.19
Netj200_A5: j200.A5 R204.1 | length 105.5
  Top Layer w10: R204.1 1236.5,1388.5 1259.1,1365.9 1259.1,1345.48 1278.66,1325.91 1278.66,1303.23 j200.A5
Netj200_B5: j200.B5 R205.1 | length 108.1
  Top Layer w10: j200.B5 1397.68,1339.96 1415.2,1357.48 1415.48,1357.48 1446.5,1388.5 R205.1
Netj201_A5: j201.A5 R210.1 | length 112.5
  Top Layer w12: R210.1 1820,1398.5 1855.79,1362.71 j201.A5
Netj201_A6: j201.A6 j201.B6 U202.1 | length 322.3
  Top Layer w12: U202.1 1862.6,1423.37 1895.16,1390.81 j201.A6 1895.25,1302.23 1895.25,1278.13 1905.7,1267.68 1923.99,1267.68 1934.43,1278.13 1934.43,1302.23 j201.B6
Netj201_A7: j201.A7 j201.B7 U202.3 | length 369.3
  Top Layer w12: v1(1870,1380) 1870,1378.38 1875.47,1372.9 j201.B7 ; j201.A7 1914.84,1395.81 1937.4,1418.37 U202.3
  Bottom Layer w12: v1(1870,1380) 1871.15,1378.85 1896.15,1378.85 v1(1925,1350)
Netj201_B5: j201.B5 R211.1 | length 79.3
  Top Layer w12: R211.1@1970,1380 1970,1342 1973.8,1338.2 1973.8,1302.42 j201.B5
NetR202_1: R202.1 R203.2 U201.8 | length 373
  Top Layer w10: R203.2 1351.5,1746.5 R202.1 R202.1@1355,1750 ; U201.8 1571.06,1708.07 1571.06,1681.04 1577.47,1674.64 v1(1577.47,1672.47)
  Top Layer w12: R202.1@1355,1750 v1(1385,1750)
  Bottom Layer w12: v1(1385,1750) 1462.53,1672.47 1518.59,1672.47 1520.06,1671 1539.94,1671 1541.41,1672.47 v1(1577.47,1672.47)
NetR206_2: R206.2 U201.9 | length 449.3
  Top Layer w12: R206.2 1350,1888.5 1362.5,1876 1389,1876 v1(1390,1875) ; U201.9 1589.94,1708.88 1589.94,1689.7 1603.49,1676.15 1613.85,1676.15 v1(1615,1675)
  Bottom Layer w12: v1(1390,1875) 1495,1770 1595,1770 1615,1750 v1(1615,1675)
NetR208_2: R208.2 U203.16 | length 165.9
  Top Layer w10: R208.2@2240,1138.5 R208.2 U203.16
NetR209_1: R209.1 U203.7 | length 253.1
  Top Layer w10: U203.7 3105.79,1376.93 3133.86,1405 v1(3135,1405) ; R209.1 3270,1426.5 v1(3270,1455)
  Bottom Layer w10: v1(3135,1405) 3175,1405 3225,1455 v1(3270,1455)
NetU203_5: U203.5 U300.3 | length 717
  Top Layer w12: U203.5 3105.79,1258.82 3141.01,1294.04 3154.5,1294.04 3175,1314.54 3175,1447.43 3178,1450.43 3178,1457.54 3320,1599.54 3320,1765 3305,1780 3265,1780 3252.86,1767.86 3252.86,1747.86 U300.3
NetU203_6: U203.6 U300.4 | length 556.2
  Top Layer w12: U203.6 3149.97,1317.87 3157,1324.9 3157,1454.88 3160,1457.88 3160,1465 3301,1606 3301,1683.35 3275.59,1708.76 U300.4
Solar_VIN: D102.2 Panel.1 | length 180
  Top Layer w24: Panel.1 1211.4,2528.1 1261.44,2478.06 1261.44,2435.56 D102.2
STDBY: 100.6 D101.2 | length 466.9
  Top Layer w10: D101.2 1627.28,2675 1635.22,2682.94 1635.22,2707.59 1680.63,2753 1783.27,2753 1797.09,2766.83 1822.91,2766.83 1835,2754.73 1835,2699.83 1847.09,2687.74 1887.19,2687.74 1910,2710.55 100.6
USB_CP_D_N: U200.6 U201.5 | length 314.3
  Top Layer w15: U200.6 1277.6,1617.32 1288.7,1606.22 1288.7,1602.68 1300.35,1591.03 1367.04,1591.03 1500,1723.99 1500,1735
USB_CP_D_P: U200.4 U201.4 | length 250.7
  Top Layer w15: U200.4 1352.4,1681.7 1387.4,1681.7 1465.86,1760.16 U201.4
USB_O_CP_D_N: j200.A7 j200.B7 U200.1 | length 309.9
  Top Layer w15: U200.1 1277.6,1354.64 1298.97,1333.27 1298.97,1302.6 1299.35,1302.23 1299.35,1278.13 1299.53,1277.94 1299.53,1275.82 1309.17,1266.18 1328.7,1266.18 1338.34,1275.82 1338.34,1277.94 1338.53,1278.13 j200.A7@1338.53,1285.68
USB_O_CP_D_P: j200.A6 j200.B6 U200.3 | length 263.1
  Top Layer w15: 1323.98,1333.59 1328.85,1338.46 1355.35,1338.46 1358.24,1341.35 ; U200.3 1357.7,1514.59 1357.7,1493.55 1358.24,1493 1358.24,1422.34 1351.5,1415.59 1351.5,1364.41 1358.24,1357.66 1358.24,1341.35 ; j200.B6 1358.31,1341.29 1358.24,1341.35
VBUS_ESP: j200.A4/B9 j200.B4/A9 R202.2 U200.5 | length 873
  Top Layer w10: R202.2 1287,1743.5 1287,1670.91 1314.99,1642.92 U200.5
  Top Layer w12: R202.2@1287,1743.5 1206,1662.5 1206,1365.03 1217.03,1354 1223.26,1354 1234.29,1342.96 j200.A4/B9 1240.1,1296.51 1240.1,1278.32 1271.74,1246.68 1385.82,1246.68 1417.46,1278.32 1417.46,1296.51 j200.B4/A9
VUSB: 100.4 100.8 C101.1 D102.1 j201.A4/B9 j201.B4/A9 U202.5 | length 2766.9
  Top Layer w12: j201.A4/B9 1816.32,1296.51 1816.32,1278.32 1826.96,1267.68 1880.24,1267.68 1898.24,1249.68 1931.44,1249.68 1949.44,1267.68 1983.04,1267.68 1993.68,1278.32 1993.68,1296.51 j201.B4/A9
  Top Layer w24: D102.1 1606.93,2390 1673.84,2456.91 1713.28,2456.91 1780.19,2523.82 1780.19,2545.26 1808.75,2573.82 1854.56,2573.82 1876.74,2596 ; 100.8 1810,2662.74 1876.74,2596 ; j201.A4/B9 1810.32,1302.51 1810.32,1327.46 1787.02,1350.76 1713.3,1350.76 1690,1374.06 1690,1512.61 1846.09,1668.71 1879.1,1668.71 1899.2,1648.61 1899.2,1625.91 1900.79,1627.5 1900.79,1654.39 2115,1868.61 2115,2265 2107.09,2272.91 2107.09,2297.91 v1(2100,2305) ; 1911.25,2573.82 1965.04,2520.02 v1(1965.04,2474.96) 1965.04,2446.46 C101.1 ; 1913.25,2575.82 1893.07,2596 1876.74,2596
  Bottom Layer w24: v1(1965.04,2474.96) 2100,2340 v1(2100,2305)
pads on no net: j200. j200.A8 j200.B8 j201. j201.A8 j201.B8 U100.4 U201.1 U201.2 U201.10 U201.11 U201.13 U201.14 U201.15 U201.16 U203.3 U203.4 U203.10 U203.15 U203.17 U203.18 U301.6

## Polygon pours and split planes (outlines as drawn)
GND on Bottom Layer "GND_BOTTOM" (solid, pour order 1): 997.15,1003.59 3405,1003.59 3405.4,1007.11 3405,2829.6 3405,2830 997.15,2830
GND on Top Layer "GND_TOP" (solid, pour order 0): 997.15,1003.59 3405,1003.59 3405.4,1007.11 3405.4,2830 3405,2830.4 997.15,2830

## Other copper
Top Layer:
  drawing of 152 lines, arcs and shapes, not listed

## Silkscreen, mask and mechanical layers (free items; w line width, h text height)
Top Overlay:
  text "GND" at 1125.32,2680 h30 r270
  text "Solar_VIN" at 1125.31,2580 h30 r270
  text "ESP_TX_0" at 2375,2365.31 h30
  text "ESP_RX_0" at 2525,2365.31 h30
  text "ESP_BOOT" at 2675,2365.31 h30
  text "GND" at 2830,2365.32 h30
  text "ESP_RST" at 2915,2365.31 h30
  text "GND" at 3060,2365.32 h30
  text "3.3V_ESP" at 1630,2110.31 h30
  text "GND" at 1780,2110.32 h30
  text "I2C_SCL" at 1860,2110.31 h30
  text "I2C_SDA" at 1990,2110.31 h30
  text "ESP_BOOT" at 2580,1985.31 h30
  text "ESP_RST" at 2885,1985.31 h30
  text "ESP_D_N" at 1930.31,1785 h30 r270
  text "ESP_D_P" at 1850.31,1780 h30 r270
  text "ESP32C3" at 2495,1545.32 h30
  text "USBC_ESP" at 2110,1280.31 h30
  text "INPUT POWER" at 2110,1250.32 h30
  text "UART" at 1050,1190.32 h30
Board Shape:
  lines w12.5: 3405,1003.59 997.15,1003.59 997.15,2830 3405.4,2830 3405.4,2762.11 3405.4,1592.11 3405.4,1007.11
